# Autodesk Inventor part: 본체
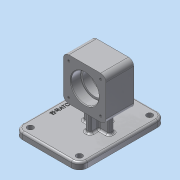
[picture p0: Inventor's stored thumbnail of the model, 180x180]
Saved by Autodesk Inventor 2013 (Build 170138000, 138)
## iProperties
Created: 2020-11
Part Number: 본체
Material: 알루미늄 6061
Document SubType Name: Modeling
Designer: Administrator
Density: 2.71 g/cm^3
Mass: 685.745 g
Surface Area: 542.794 cm^2
Volume: 253.042 cm^3
Author: Administrator
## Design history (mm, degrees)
sketch "스케치1"
  geometry: L1 (53, -49)-(-53, -49); L2 (-65, -37)-(-65, 37); L3 (-53, 49)-(53, 49); L4 (65, 37)-(65, -37); L5 (65, -49)-(-65, 49); L6 (-65, -49)-(65, 49); A1 r 12 centre (53, 37) between (65, 37) and (53, 49); A2 r 12 centre (53, -37) between (53, -49) and (65, -37); A3 r 12 centre (-53, -37) between (-65, -37) and (-53, -49); A4 r 12 centre (-53, 37) between (-53, 49) and (-65, 37); 1 further point
  constraints: 12 end point, 8 point on circle, 8 point on line, 8 tangent, 4 centre point, 3 equal radius, 2 midpoint, 2 parallel, 1 horizontal, 1 perpendicular
  dimensions: "d0" = 130 distance of L6.end L5.end; "d2" = 98 distance of L5.start L6.end; "d3" = 12 radius of A1
extrude "돌출1" new body sketch "스케치1" distance "d4" = 10; taper "d5" = 0 deg
node "작업 평면1"
sketch "스케치3"
  geometry: L1 (-21, 19)-(21, 19); L2 (21, 19)-(21, -45); L3 (21, -45)-(-21, -45); L4 (-21, -45)-(-21, 19); L5 (-21, 19)-(21, -45); L6 (21, 19)-(-21, -45); L7 (65, -37)-(65, 37) reference; L8 (53, 49)-(-53, 49) reference; 2 further points
  constraints: 12 end point, 2 midpoint, 2 parallel, 1 horizontal, 1 perpendicular
  dimensions: "d7" = 65 distance from line of point (0, -13) L7; "d9" = 62 distance from line of L8 point (0, -13); "d10" = 42 distance of L1.end L1.start; "d11" = 64 distance of L2.end L1.end
extrude "돌출2" join sketch "스케치3" stored distance "d12" = 64; taper "d13" = 0 deg
fillet "모깎기1" dims "d14" = 8
sketch "스케치4"
  geometry: L1 (65, 37)-(65, -37) reference; L2 (-53, 49)-(53, 49) reference; L3 (-4, 7)-(4, 7); L4 (4, 7)-(4, -33); L5 (4, -33)-(-4, -33); L6 (-4, -33)-(-4, 7); L7 (-4, 7)-(4, -33); L8 (4, 7)-(-4, -33); 1 further point
  constraints: 12 end point, 2 midpoint, 2 parallel, 1 horizontal, 1 perpendicular
  dimensions: "d91" = 65 distance from line of L1 point (0, -13); "d92" = 62 distance from line of point (0, -13) L2; "d93" = 8 distance of L3.end L3.start; "d94" = 40 distance of L5.end L3.start
extrude "돌출3" join sketch "스케치4" stored distance "d20" = 64; taper "d21" = 0 deg
sketch "스케치5"
  geometry: L1 (65, 37)-(65, -37) reference; L2 (-53, 49)-(53, 49) reference; L3 (17, -17)-(-17, -17); L4 (-17, -17)-(-17, -9); L5 (-17, -9)-(17, -9); L6 (17, -9)-(17, -17); L7 (17, -17)-(-17, -9); L8 (-17, -17)-(17, -9); 1 further point
  constraints: 12 end point, 2 midpoint, 2 parallel, 1 horizontal, 1 perpendicular
  dimensions: "d95" = 34 distance of L5.end L4.end; "d97" = 8 distance of L3.end L4.end; "d98" = 65 distance from line of L1 point (0, -13); "d99" = 62 distance from line of L2 point (0, -13)
extrude "돌출4" join sketch "스케치5" stored distance "d27" = 64; taper "d28" = 0 deg
node "작업 평면2"
sketch "스케치6"
  geometry: L1 (0, 0)-(0, 48) reference; L2 (42, 48)-(42, 0) reference; L3 (0, 24)-(42, 24); L4 (0, 45)-(15, 45); L5 (15, 45)-(15, 42); L6 (15, 42)-(27, 42); L7 (27, 42)-(27, 45); L8 (27, 45)-(42, 45); 1 further point
  constraints: 12 end point, 3 horizontal, 3 point on line, 2 midpoint, 2 vertical
  dimensions: "d32" = 42 diameter of L4 L3; "d34" = 15 distance of L4.start L4.end; "d35" = 15 distance of L8.end L7.end; "d36" = 36 diameter of L6 L3
revolve "회전1" sketch "스케치6" stored, may be unused: angle "d37" = 90 deg
fillet "모깎기4" dims "d38" = 3
sketch "스케치7"
  geometry: L1 (-64, 0)-(-64, 48) reference; L2 (-8, -8)-(-56, -8) reference; L3 (0, 48)-(0, 0) reference; L4 (-56, 56)-(-8, 56) reference; C1 r 21 at (-32, 24) reference; A1 r 8 centre (-56, 48) between (-56, 56) and (-64, 48) reference; A2 r 8 centre (-56, 0) between (-64, 0) and (-56, -8) reference; A3 r 8 centre (-8, 0) between (-8, -8) and (0, 0) reference; A4 r 8 centre (-8, 48) between (0, 48) and (-8, 56) reference; 1 further point
hole "구멍1" sketch "스케치7" at (-8, 48), (-8, 0), (-56, 0), (-56, 48) diameter "d39" = 3.242; stored, may be unused: countersink angle "d43" = 90 deg, drill point angle "d45" = 118 deg; dims "d40" = 8, "d41" = 4, "d42" = 2, "d44" = 10
node "작업 평면3"
hole "구멍2" diameter "d49" = 9; stored, may be unused: countersink angle "d53" = 90 deg, drill point angle "d55" = 0 deg; dims "d47" = 10, "d48" = 10, "d50" = 8, "d51" = 4, "d52" = 2, "d54" = 10
hole "구멍3" diameter "d58" = 9; stored, may be unused: countersink angle "d62" = 90 deg, drill point angle "d64" = 0 deg; dims "d56" = 10, "d57" = 10, "d59" = 8, "d60" = 4, "d61" = 2, "d63" = 10
hole "구멍4" diameter "d67" = 9; stored, may be unused: countersink angle "d71" = 90 deg, drill point angle "d73" = 0 deg; dims "d65" = 10, "d66" = 10, "d68" = 8, "d69" = 4, "d70" = 2, "d72" = 10
hole "구멍5" diameter "d76" = 9; stored, may be unused: countersink angle "d80" = 90 deg, drill point angle "d82" = 0 deg; dims "d74" = 10, "d75" = 10, "d77" = 8, "d78" = 4, "d79" = 2, "d81" = 10
sketch "스케치8"
  geometry: L1 (53, 49)-(-53, 49) reference; L2 (65, -37)-(65, 37) reference; 2 further points
  constraints: 1 other
  dimensions: "d83" = 10 distance from line of L1 point (0, 39); "d84" = 65 distance from line of point (0, 39) L2
feature "엠보싱1" sketch "스케치8" dims "d0" = 130, "d2" = 98, "d3" = 12, "d85" = 0.5, "d86" = 0
chamfer "모따기1" distance "d87" = 1; stored, may be unused: second distance "d88" = 2, angle "d89" = 45 deg
fillet "모깎기5" dims "d90" = 0.3
fillet "모깎기6" dims "d100" = 3
fillet "모깎기7" dims "d101" = 3
node "솔리드1"
mirror "대칭1"
node "투영된 루프1"
other parameters: "d31" = -32, "d46" = -21
